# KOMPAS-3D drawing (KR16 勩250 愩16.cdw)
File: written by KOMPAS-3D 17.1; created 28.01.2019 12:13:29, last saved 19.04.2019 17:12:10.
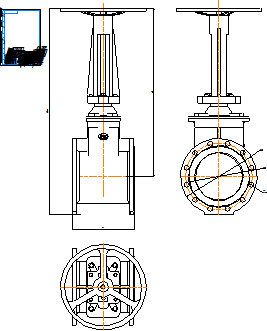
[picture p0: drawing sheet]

Sheet 1: A4, portrait

Title block, sheet 1: name: KR16 Ду250 Ру16; material: Внимание! Данный продукт является объектом авторского права ООО «Торговый Дом АДЛ». / Запрещается изменение, копирование, распространение / (в том числе путем копирования на другие сайты и ресурсы в Интернете) / или любое иное использование информации и объектов без предварительного / согласия правообладателя (ООО «Торговый Дом АДЛ»).; sheets: 1; organisation: ООО "Торговый дом АДЛ"; sheet format: A4; stored path: \\adlc.lan\data\АДЛ_ПКД\3D-модели\ADL production\Клиновые задвижки серии KR ГРАНАР\Клиновые задвижки KR16\Со штурвалом\KOMPAS 2D\KR16 Ду250.cdw

Views: Вид 1, Проекционный вид 2
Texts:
  user
Dimensions and other numbers on the sheet: 330; 1093,5; 891; 405; 355; 26; 12 отв.; 1:1; 1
